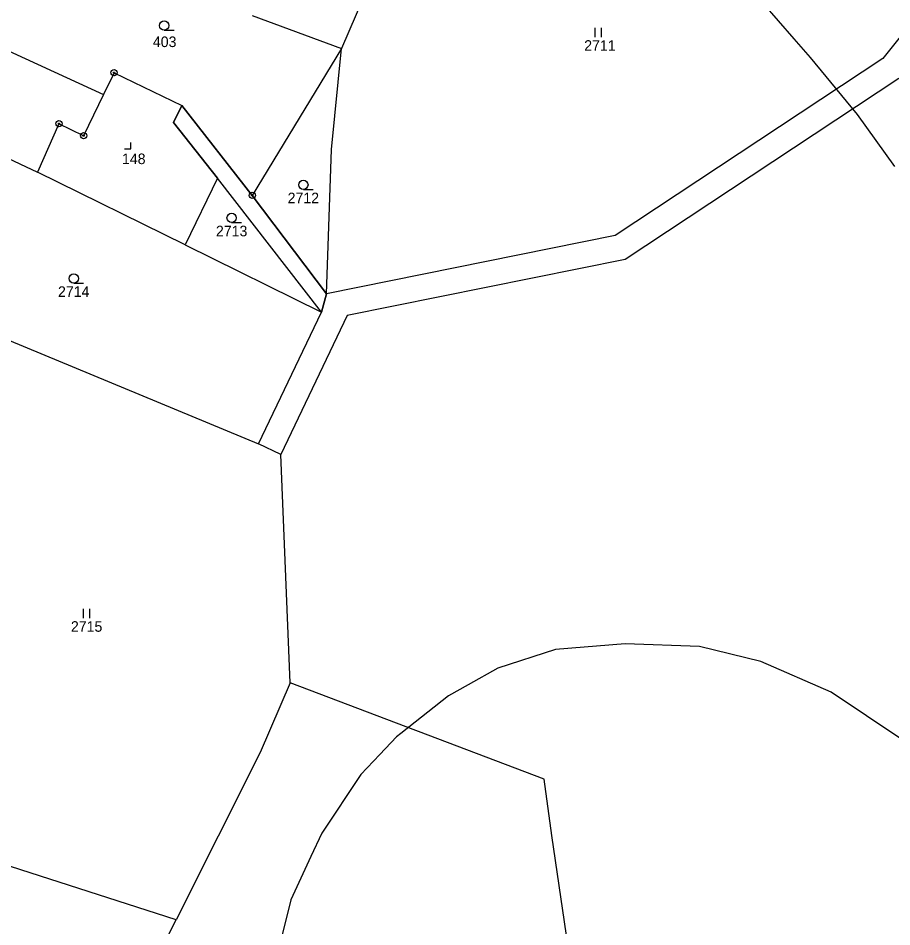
# Model space of a CAD drawing. Extents: x -546762 to -540209, y -1046851 to -1035694.
# Drawn here: x -542448.6 to -542308.1, y -1039277.1 to -1039131 of the extents above; entities that cross this region are included whole.
import ezdxf

# ---------------------------------------------------------------- set-up
doc = ezdxf.new("R2010")
doc.units = 0
for name, color, linetype in [('Vrstva 1', 7, 'Continuous'), ('Vrstva 18', 7, 'Continuous'), ('Vrstva 19', 7, 'Continuous'), ('Vrstva 24', 7, 'Continuous'), ('Vrstva 25', 7, 'Continuous'), ('Vrstva 30', 7, 'Continuous'), ('Vrstva 52', 7, 'Continuous')]:
    doc.layers.add(name, color=color, linetype=linetype)

msp = doc.modelspace()

# ---------------------------------------------------------------- linework, layer by layer
at = {"layer": 'Vrstva 1'}
for p, q in [((-542410.99, -1039130.59), (-542396.61, -1039135.93)), ((-542433.2, -1039139.8), (-542434.9, -1039143.31)), ((-542434.9, -1039143.31), (-542438.1, -1039149.93)), ((-542442.06, -1039148.01), (-542445.52, -1039155.81)), ((-542438.1, -1039149.93), (-542442.06, -1039148.01))]:
    msp.add_line(p, q, dxfattribs=at)
for points in [[(-542390.54, -1039121.83), (-542396.61, -1039135.93)], [(-542301.62, -1039127.53), (-542309.54, -1039137.51)], [(-542453.5, -1039134.8), (-542434.9, -1039143.31)], [(-542396.61, -1039135.93), (-542410.98, -1039159.52)], [(-542398.25, -1039152.17), (-542396.61, -1039135.93)], [(-542309.54, -1039137.51), (-542352.61, -1039165.98)], [(-542433.2, -1039139.8), (-542422.32, -1039145.07)], [(-542307.01, -1039140.76), (-542351.01, -1039169.85)], [(-542469.2, -1039144.65), (-542445.52, -1039155.81)], [(-542422.32, -1039145.07), (-542423.64, -1039147.79)], [(-542410.98, -1039159.52), (-542422.32, -1039145.07)], [(-542423.64, -1039147.79), (-542416.59, -1039156.76)], [(-542399.06, -1039175.35), (-542398.25, -1039152.17)], [(-542421.78, -1039167.49), (-542445.52, -1039155.81)], [(-542416.59, -1039156.76), (-542421.78, -1039167.49)], [(-542399.06, -1039175.35), (-542410.98, -1039159.52)], [(-542352.61, -1039165.98), (-542399.06, -1039175.35)], [(-542421.78, -1039167.49), (-542399.86, -1039178.3)], [(-542351.01, -1039169.85), (-542395.69, -1039178.86)], [(-542399.86, -1039178.3), (-542399.06, -1039175.35)], [(-542409.99, -1039199.48), (-542399.86, -1039178.3)], [(-542395.69, -1039178.86), (-542406.38, -1039201.21)], [(-542452.91, -1039181.69), (-542409.99, -1039199.48)], [(-542406.38, -1039201.21), (-542409.99, -1039199.48)], [(-542404.87, -1039237.88), (-542406.38, -1039201.21)], [(-542404.87, -1039237.88), (-542409.68, -1039249.09)], [(-542364.02, -1039253.41), (-542404.87, -1039237.88)], [(-542409.68, -1039249.09), (-542423.21, -1039275.98)], [(-542362.78, -1039262.42), (-542364.02, -1039253.41)], [(-542359.59, -1039284.36), (-542362.78, -1039262.42)], [(-542423.21, -1039275.98), (-542454.56, -1039265.95)], [(-542442.71, -1039314.76), (-542423.21, -1039275.98)]]:
    msp.add_lwpolyline(points, dxfattribs=at)
at = {"layer": 'Vrstva 24'}
for centre, radius in [((-542433.2, -1039139.8), 0.5), ((-542433.2, -1039139.8), 0.1), ((-542442.06, -1039148.01), 0.5), ((-542442.06, -1039148.01), 0.1), ((-542438.1, -1039149.93), 0.5), ((-542438.1, -1039149.93), 0.1), ((-542410.98, -1039159.52), 0.5), ((-542410.98, -1039159.52), 0.1)]:
    msp.add_circle(centre, radius, dxfattribs=at)
at = {"layer": 'Vrstva 25'}
for p, q in [((-542355.83, -1039134.07), (-542355.83, -1039132.57)), ((-542354.83, -1039134.07), (-542354.83, -1039132.57)), ((-542425.14, -1039132.98), (-542423.54, -1039132.98)), ((-542402.76, -1039158.58), (-542401.16, -1039158.58)), ((-542414.29, -1039163.9), (-542412.69, -1039163.9)), ((-542439.69, -1039173.64), (-542438.09, -1039173.64)), ((-542438.11, -1039227.48), (-542438.11, -1039225.98)), ((-542437.11, -1039227.48), (-542437.11, -1039225.98))]:
    msp.add_line(p, q, dxfattribs=at)
msp.add_lwpolyline([(-542431.5, -1039152.02), (-542430.5, -1039152.02), (-542430.5, -1039151.02)], dxfattribs=at)
for centre in [(-542425.14, -1039132.23), (-542402.76, -1039157.83), (-542414.29, -1039163.15), (-542439.69, -1039172.89)]:
    msp.add_circle(centre, 0.75, dxfattribs=at)
at = {"layer": 'Vrstva 30'}
msp.add_lwpolyline([(-542399.86, -1039178.3), (-542416.59, -1039156.76), (-542423.64, -1039147.79), (-542422.32, -1039145.07), (-542410.98, -1039159.52), (-542399.06, -1039175.35), (-542399.86, -1039178.3)], dxfattribs=at)
at = {"layer": 'Vrstva 52'}
for points in [[(-542410.09, -1039015.31), (-542404.21, -1039024.18), (-542400.47, -1039029.84), (-542397.83, -1039033.82), (-542390.6, -1039044.72), (-542390.56, -1039044.79), (-542388.96, -1039047.36), (-542383.6, -1039055.99), (-542380.67, -1039060.71), (-542375.7, -1039068.73), (-542375.18, -1039069.56), (-542358.98, -1039093.36), (-542355.32, -1039098.01), (-542353.15, -1039100.77), (-542350.59, -1039104.02), (-542344.53, -1039111.73), (-542338.7, -1039117.91), (-542334.2, -1039122.69), (-542331.46, -1039125.6), (-542323.89, -1039134.33), (-542321.27, -1039137.36), (-542313.69, -1039146.52), (-542307.68, -1039154.89)], [(-542306.5, -1039247.03), (-542317.85, -1039239.41), (-542329.2, -1039234.48), (-542339.06, -1039232.08), (-542351.01, -1039231.64), (-542362.21, -1039232.53), (-542371.48, -1039235.52), (-542376.26, -1039238.23), (-542379.39, -1039240), (-542387.1, -1039246.06), (-542387.76, -1039246.58), (-542390.46, -1039249.42), (-542393.51, -1039252.63), (-542399.78, -1039262.05), (-542401.53, -1039265.82), (-542404.75, -1039272.77), (-542407.88, -1039285.33), (-542409.45, -1039305.2), (-542409.45, -1039321.94), (-542408.98, -1039327.9), (-542407.83, -1039342.38), (-542407.49, -1039346.72)]]:
    msp.add_lwpolyline(points, dxfattribs=at)

# ---------------------------------------------------------------- texts
at = {"layer": 'Vrstva 18'}
for s, p in [('403', (-542426.96, -1039135.68)), ('2711', (-542357.59, -1039136.28)), ('2712', (-542405.29, -1039160.79)), ('2713', (-542416.82, -1039166.11)), ('2714', (-542442.22, -1039175.85)), ('2715', (-542440.14, -1039229.69))]:
    msp.add_text(s, height=1.7, dxfattribs=at).set_placement(p)
at = {"layer": 'Vrstva 19'}
msp.add_text('148', height=1.7, dxfattribs=at).set_placement((-542431.93, -1039154.5))

doc.saveas('drawing.dxf')
